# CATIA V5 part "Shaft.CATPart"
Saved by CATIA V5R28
Part number: Shaft
Material "DS Dark Green": density 7860 kg/m3, Young's modulus 2e+11 Pa, Poisson ratio 0.266
Bounding box of the stored display mesh (mm): x -15 to 15, y -100 to 0, z -15 to 15
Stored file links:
  C:\Users\Parisa\Desktop\tarah sanat\Universal Coupling\Shaft.CATPart
  C:\Program Files\Dassault Systemes\B28\win_b64\startup\materials\green_env_512x512.jpg
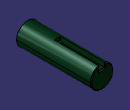
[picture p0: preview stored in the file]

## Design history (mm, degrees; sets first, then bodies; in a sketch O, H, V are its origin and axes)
Body1 "Shaft" (main body), material "DS Dark Green"
  Sketch1 on zx-plane, origin (0, 0, 0), H (-1, 0, 0), V (0, 0, 1)
    circle A1 centre (0, 0) radius 15
    radius A1 = 15
  Pad1: profile Sketch1, direction (0, -1, 0), length 100
  Sketch2 on start face of Pad1, origin (0, 0, 0), H (-1, 0, 0), V (0, 0, 1)
    point P1 (0, 11.5)
    line L1 (4, 15) -> (4, 8)
    line L2 (4, 8) -> (-4, 8)
    line L3 (-4, 8) -> (-4, 15)
    line L4 (-4, 15) -> (4, 15)
    length L1 = 7
    length L4 = 8
    distance P1 H = 11.5
    coincidence: P1 V
    vertical: L1 V, L3 V
    horizontal: L2 H, L4 H
    equidistance: L1 L3 P1, L2 L4 P1
  Pocket1: profile Sketch2, direction (0, -1, 0), length 60
  Fillet1: radius 3, on edge [face of Pocket1 from Sketch2.L2 | end face of Pocket1]
  Chamfer1: length 1, angle 45, on start face of Pad1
